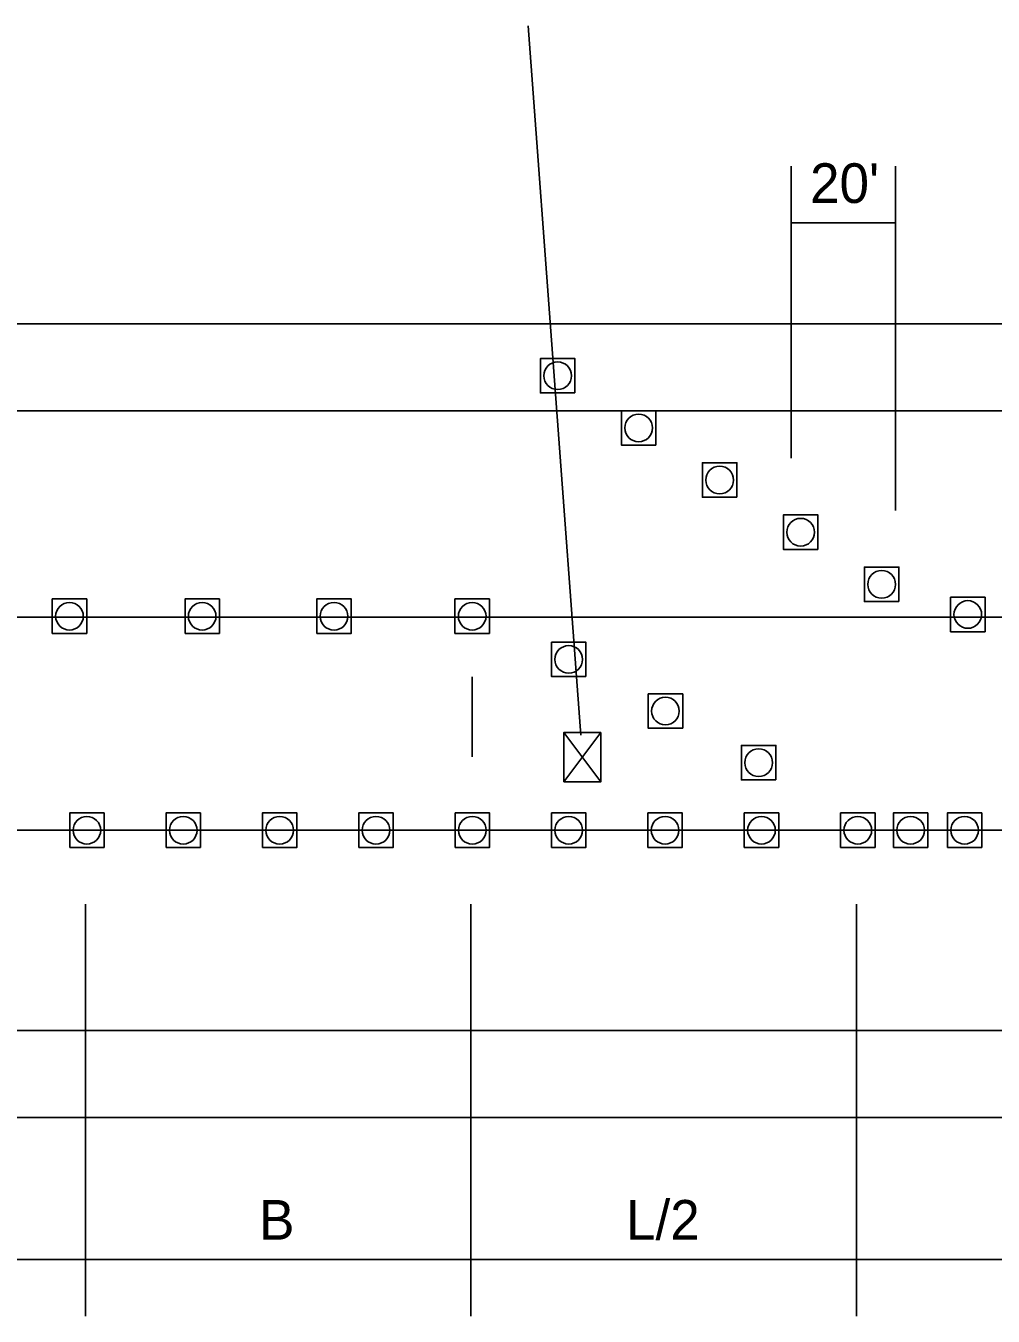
# Model space of a CAD drawing. Extents: x 99988 to 100172, y 99995 to 100047.
# Drawn here: x 100005.575 to 100007.282, y 100004.263 to 100006.54 of the extents above; entities that cross this region are included whole.
import ezdxf

# ---------------------------------------------------------------- set-up
doc = ezdxf.new("R2010")
doc.units = 0
for name, color, linetype in [('Default', 7, 'Continuous'), ('Level 15', 7, 'Continuous'), ('Level 20', 7, 'Continuous'), ('TR_WZ_TrafficSafetyCone', 7, 'Continuous'), ('TR_WZ_WorkZoneDetails', 7, 'Continuous')]:
    doc.layers.add(name, color=color, linetype=linetype)

msp = doc.modelspace()

# ---------------------------------------------------------------- linework, layer by layer
at = {"layer": 'Default'}
for p, q in [((100011.7483, 100005.4964), (100005.4457, 100005.4964)), ((100006.5898, 100005.2932), (100006.5245, 100005.2061)), ((100006.5245, 100005.2932), (100006.5898, 100005.2061)), ((100006.5572, 100005.2497), (100006.5572, 100005.2497)), ((100006.5573, 100005.2498), (100006.5573, 100005.2498)), ((100012.5819, 100005.1207), (100002.4254, 100005.1207))]:
    msp.add_line(p, q, dxfattribs=at)
msp.add_lwpolyline([(100006.5898, 100005.2932), (100006.5245, 100005.2932), (100006.5245, 100005.2061), (100006.5898, 100005.2061)], close=True, dxfattribs=at)
at = {"layer": 'Level 15'}
for p, q in [((100006.9256, 100006.1922), (100007.0177, 100006.1922)), ((100007.1097, 100006.1922), (100007.0177, 100006.1922)), ((100005.6799, 100004.3634), (100005.1813, 100004.3634)), ((100005.6799, 100004.3634), (100006.0201, 100004.3634)), ((100006.3603, 100004.3634), (100006.0201, 100004.3634)), ((100006.3603, 100004.3634), (100006.7006, 100004.3634)), ((100007.041, 100004.3634), (100006.7006, 100004.3634)), ((100007.041, 100004.3634), (100008.2472, 100004.3634))]:
    msp.add_line(p, q, dxfattribs=at)
at = {"layer": 'TR_WZ_TrafficSafetyCone'}
for points in [[(100006.5437, 100005.892), (100006.5437, 100005.9528), (100006.4829, 100005.9528), (100006.4829, 100005.892)], [(100006.6867, 100005.8001), (100006.6867, 100005.8608), (100006.6259, 100005.8608), (100006.6259, 100005.8001)], [(100006.8296, 100005.7081), (100006.8296, 100005.7688), (100006.7689, 100005.7688), (100006.7689, 100005.7081)], [(100006.9726, 100005.6161), (100006.9726, 100005.6768), (100006.9119, 100005.6768), (100006.9119, 100005.6161)], [(100007.1156, 100005.5241), (100007.1156, 100005.5848), (100007.0549, 100005.5848), (100007.0549, 100005.5241)], [(100005.6214, 100005.4678), (100005.6821, 100005.4678), (100005.6821, 100005.5286), (100005.6214, 100005.5286)], [(100005.8556, 100005.4678), (100005.9163, 100005.4678), (100005.9163, 100005.5286), (100005.8556, 100005.5286)], [(100006.0882, 100005.4678), (100006.1489, 100005.4678), (100006.1489, 100005.5286), (100006.0882, 100005.5286)], [(100006.3929, 100005.4678), (100006.3929, 100005.5286), (100006.3321, 100005.5286), (100006.3321, 100005.4678)], [(100007.207, 100005.4709), (100007.2677, 100005.4709), (100007.2677, 100005.5316), (100007.207, 100005.5316)], [(100006.5633, 100005.3917), (100006.5633, 100005.4524), (100006.5025, 100005.4524), (100006.5025, 100005.3917)], [(100006.734, 100005.3006), (100006.734, 100005.3613), (100006.6732, 100005.3613), (100006.6732, 100005.3006)], [(100006.8985, 100005.2095), (100006.8985, 100005.2702), (100006.8378, 100005.2702), (100006.8378, 100005.2095)], [(100005.6521, 100005.0904), (100005.7128, 100005.0904), (100005.7128, 100005.1511), (100005.6521, 100005.1511)], [(100005.8221, 100005.0904), (100005.8829, 100005.0904), (100005.8829, 100005.1511), (100005.8221, 100005.1511)], [(100005.9922, 100005.0904), (100006.053, 100005.0904), (100006.053, 100005.1511), (100005.9922, 100005.1511)], [(100006.1624, 100005.0904), (100006.2231, 100005.0904), (100006.2231, 100005.1511), (100006.1624, 100005.1511)], [(100006.3325, 100005.0904), (100006.3932, 100005.0904), (100006.3932, 100005.1511), (100006.3325, 100005.1511)], [(100006.5025, 100005.0904), (100006.5633, 100005.0904), (100006.5633, 100005.1511), (100006.5025, 100005.1511)], [(100006.6726, 100005.0904), (100006.7334, 100005.0904), (100006.7334, 100005.1511), (100006.6726, 100005.1511)], [(100006.8428, 100005.0904), (100006.9035, 100005.0904), (100006.9035, 100005.1511), (100006.8428, 100005.1511)], [(100007.0735, 100005.0904), (100007.0735, 100005.1511), (100007.0128, 100005.1511), (100007.0128, 100005.0904)], [(100007.1059, 100005.0904), (100007.1667, 100005.0904), (100007.1667, 100005.1511), (100007.1059, 100005.1511)], [(100007.2012, 100005.0904), (100007.262, 100005.0904), (100007.262, 100005.1511), (100007.2012, 100005.1511)]]:
    msp.add_lwpolyline(points, close=True, dxfattribs=at)
for centre in [(100006.5133, 100005.9224), (100006.6563, 100005.8304), (100006.7993, 100005.7384), (100006.9423, 100005.6464), (100007.0852, 100005.5544), (100005.6517, 100005.4982), (100005.8859, 100005.4982), (100006.1186, 100005.4982), (100006.3625, 100005.4982), (100007.2373, 100005.5013), (100006.5329, 100005.422), (100006.7036, 100005.3309), (100006.8681, 100005.2398), (100005.6824, 100005.1207), (100005.8525, 100005.1207), (100006.0226, 100005.1207), (100006.1927, 100005.1207), (100006.3628, 100005.1207), (100006.5329, 100005.1207), (100006.703, 100005.1207), (100006.8731, 100005.1207), (100007.0431, 100005.1207), (100007.1363, 100005.1207), (100007.2316, 100005.1207)]:
    msp.add_circle(centre, 0.0244, dxfattribs=at)
at = {"layer": 'TR_WZ_WorkZoneDetails'}
for p, q in [((100006.4614, 100006.5397), (100006.5544, 100005.2882)), ((100006.9256, 100005.7768), (100006.9256, 100006.2922)), ((100007.1097, 100005.6848), (100007.1097, 100006.2922)), ((100007.3972, 100006.0142), (100002.4293, 100006.0142)), ((100007.3972, 100005.8608), (100002.4254, 100005.8608)), ((100006.3625, 100005.3911), (100006.3625, 100005.2501)), ((100005.6799, 100004.2635), (100005.6799, 100004.9904)), ((100006.3603, 100004.2635), (100006.3603, 100004.9904)), ((100007.041, 100004.2635), (100007.041, 100004.9904)), ((100011.7483, 100004.7676), (100002.4278, 100004.7676)), ((100011.7483, 100004.6142), (100002.4307, 100004.6142))]:
    msp.add_line(p, q, dxfattribs=at)

# ---------------------------------------------------------------- texts
at = {"layer": 'Level 20'}
for s, p in [("20'", (100006.9588, 100006.2272)), ('B', (100005.9864, 100004.3984)), ('L/2', (100006.634, 100004.3984))]:
    msp.add_text(s, height=0.07, dxfattribs=at).set_placement(p)

doc.saveas('drawing.dxf')
